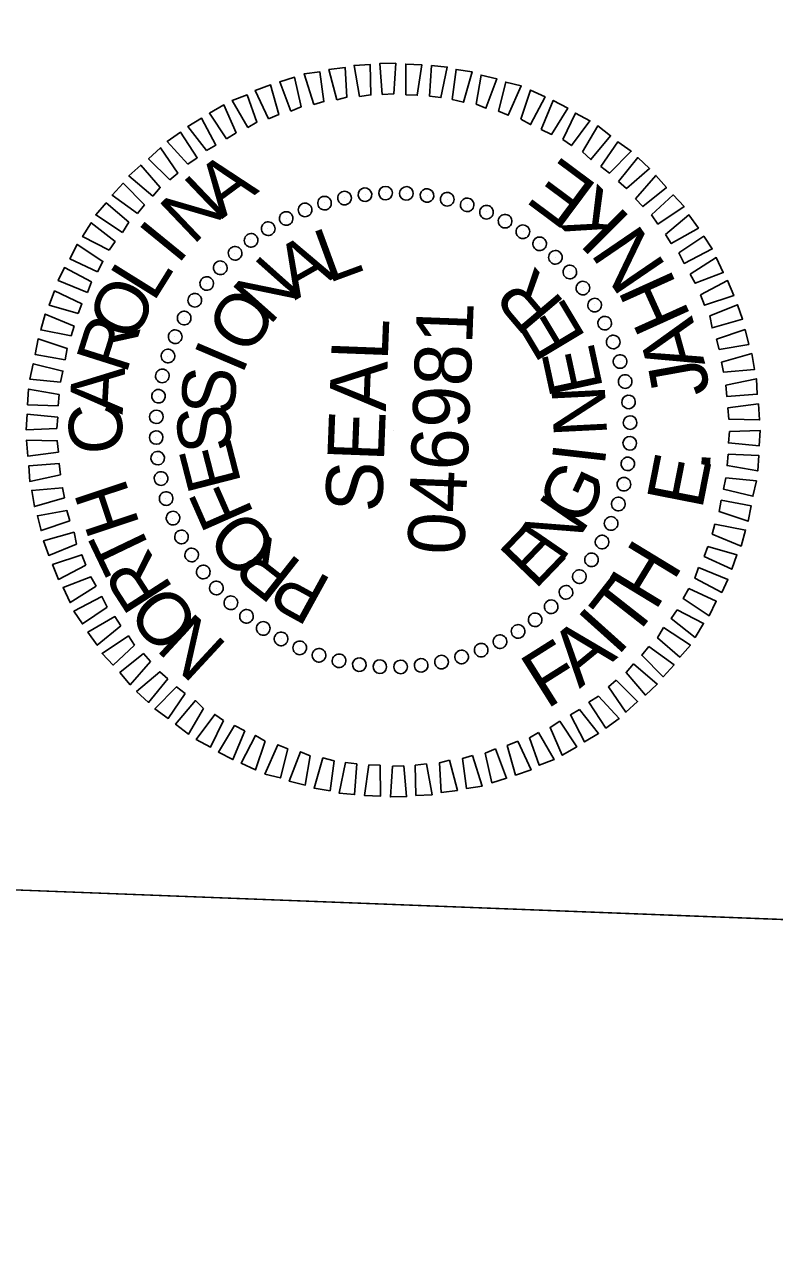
# Model space of a CAD drawing. Extents: x 2097096 to 2098260, y 686401 to 688363.
# Drawn here: x 2097223.6 to 2097303, y 687937.5 to 688066.3 of the extents above; entities that cross this region are included whole.
import ezdxf

# ---------------------------------------------------------------- set-up
doc = ezdxf.new("R2010")
doc.units = 0
for name, color, linetype in [('Sheet Layout Plan Border', 7, 'Continuous'), ('Sheet PE Seal Cell', 7, 'Continuous'), ('Sheet Profile CELL', 7, 'Continuous')]:
    doc.layers.add(name, color=color, linetype=linetype)

msp = doc.modelspace()

# ---------------------------------------------------------------- linework, layer by layer
at = {"layer": 'Sheet Layout Plan Border'}
msp.add_lwpolyline([(2098179.19, 686705.44), (2097129.59, 686735.95), (2097177.17, 687976.48), (2097364.33, 687969.3), (2097368.7, 688083.22), (2098230.76, 688050.16)], close=True, dxfattribs=at)
at = {"layer": 'Sheet PE Seal Cell'}
for p, q in [((2097259.66, 688048.29), (2097259.66, 688048.29)), ((2097261.82, 688048.51), (2097261.82, 688048.51)), ((2097264.02, 688048.47), (2097264.02, 688048.47)), ((2097255.33, 688047.46), (2097255.33, 688047.46)), ((2097257.45, 688047.98), (2097257.45, 688047.98)), ((2097266.22, 688048.24), (2097266.22, 688048.24)), ((2097268.35, 688047.81), (2097268.35, 688047.81)), ((2097270.43, 688047.28), (2097270.43, 688047.28)), ((2097251.31, 688045.81), (2097251.31, 688045.81)), ((2097253.3, 688046.73), (2097253.3, 688046.73)), ((2097272.51, 688046.5), (2097272.51, 688046.5)), ((2097249.37, 688044.73), (2097249.37, 688044.73)), ((2097274.47, 688045.52), (2097274.47, 688045.52)), ((2097276.38, 688044.45), (2097276.38, 688044.45)), ((2097247.57, 688043.55), (2097247.57, 688043.55)), ((2097278.13, 688043.13), (2097278.13, 688043.13)), ((2097245.87, 688042.12), (2097245.87, 688042.12)), ((2097244.31, 688040.62), (2097244.31, 688040.62)), ((2097279.83, 688041.71), (2097279.83, 688041.71)), ((2097281.32, 688040.16), (2097281.32, 688040.16)), ((2097242.89, 688038.93), (2097242.89, 688038.93)), ((2097282.75, 688038.45), (2097282.75, 688038.45)), ((2097241.58, 688037.18), (2097241.58, 688037.18)), ((2097283.94, 688036.65), (2097283.94, 688036.65)), ((2097240.5, 688035.27), (2097240.5, 688035.27)), ((2097285.01, 688034.71), (2097285.01, 688034.71)), ((2097239.53, 688033.3), (2097239.53, 688033.3)), ((2097285.94, 688032.72), (2097285.94, 688032.72)), ((2097238.75, 688031.23), (2097238.75, 688031.23)), ((2097286.66, 688030.69), (2097286.66, 688030.69)), ((2097238.22, 688029.15), (2097238.22, 688029.15)), ((2097287.18, 688028.57), (2097287.18, 688028.57)), ((2097237.78, 688027.01), (2097237.78, 688027.01)), ((2097287.49, 688026.36), (2097287.49, 688026.36)), ((2097237.55, 688024.82), (2097237.55, 688024.82)), ((2097287.71, 688024.2), (2097287.71, 688024.2)), ((2097237.51, 688022.62), (2097237.51, 688022.62)), ((2097262.61, 688023.41), (2097262.61, 688023.41)), ((2097287.68, 688022), (2097287.68, 688022)), ((2097237.73, 688020.46), (2097237.73, 688020.46)), ((2097287.44, 688019.81), (2097287.44, 688019.81)), ((2097238.05, 688018.25), (2097238.05, 688018.25)), ((2097287.01, 688017.67), (2097287.01, 688017.67)), ((2097238.57, 688016.13), (2097238.57, 688016.13)), ((2097286.48, 688015.59), (2097286.48, 688015.59)), ((2097239.29, 688014.1), (2097239.29, 688014.1)), ((2097285.7, 688013.52), (2097285.7, 688013.52)), ((2097240.21, 688012.11), (2097240.21, 688012.11)), ((2097284.73, 688011.55), (2097284.73, 688011.55)), ((2097241.29, 688010.17), (2097241.29, 688010.17)), ((2097283.65, 688009.64), (2097283.65, 688009.64)), ((2097242.47, 688008.37), (2097242.47, 688008.37)), ((2097282.33, 688007.89), (2097282.33, 688007.89)), ((2097243.91, 688006.66), (2097243.91, 688006.66)), ((2097280.92, 688006.2), (2097280.92, 688006.2)), ((2097245.4, 688005.11), (2097245.4, 688005.11)), ((2097279.36, 688004.7), (2097279.36, 688004.7)), ((2097247.1, 688003.69), (2097247.1, 688003.69)), ((2097277.65, 688003.27), (2097277.65, 688003.27)), ((2097248.85, 688002.37), (2097248.85, 688002.37)), ((2097275.86, 688002.09), (2097275.86, 688002.09)), ((2097250.76, 688001.3), (2097250.76, 688001.3)), ((2097273.91, 688001.01), (2097273.91, 688001.01)), ((2097252.72, 688000.32), (2097252.72, 688000.32)), ((2097254.79, 687999.54), (2097254.79, 687999.54)), ((2097269.9, 687999.36), (2097269.9, 687999.36)), ((2097271.93, 688000.09), (2097271.93, 688000.09)), ((2097256.87, 687999.01), (2097256.87, 687999.01)), ((2097259.01, 687998.58), (2097259.01, 687998.58)), ((2097261.2, 687998.35), (2097261.2, 687998.35)), ((2097263.4, 687998.31), (2097263.4, 687998.31)), ((2097265.56, 687998.53), (2097265.56, 687998.53)), ((2097267.78, 687998.84), (2097267.78, 687998.84))]:
    msp.add_line(p, q, dxfattribs=at)
for points in [[(2097254.23, 688057.86), (2097253.2, 688061.1), (2097254.86, 688061.33), (2097255.29, 688058.17)], [(2097256.65, 688058.36), (2097255.82, 688061.55), (2097257.53, 688061.78), (2097257.71, 688058.62)], [(2097259.06, 688058.72), (2097258.49, 688062), (2097260.19, 688062.08), (2097260.27, 688058.88)], [(2097261.47, 688058.93), (2097261.2, 688062.19), (2097262.9, 688062.23), (2097262.68, 688058.98)], [(2097263.97, 688058.88), (2097263.95, 688062.14), (2097265.65, 688062.07), (2097265.17, 688058.84)], [(2097266.47, 688058.74), (2097266.69, 688061.98), (2097268.34, 688061.82), (2097267.67, 688058.59)], [(2097268.86, 688058.4), (2097269.28, 688061.58), (2097270.97, 688061.32), (2097270.05, 688058.1)], [(2097249.42, 688056.34), (2097248.03, 688059.35), (2097249.65, 688059.93), (2097250.53, 688056.8)], [(2097251.8, 688057.15), (2097250.62, 688060.25), (2097252.19, 688060.74), (2097252.87, 688057.61)], [(2097271.39, 688057.9), (2097271.91, 688060.98), (2097273.6, 688060.57), (2097272.43, 688057.46)], [(2097273.76, 688057.16), (2097274.53, 688060.23), (2097276.17, 688059.82), (2097274.8, 688056.72)], [(2097247.23, 688055.42), (2097245.59, 688058.29), (2097247.16, 688058.88), (2097248.2, 688055.99)], [(2097276.13, 688056.32), (2097277.15, 688059.38), (2097278.68, 688058.67), (2097277.16, 688055.73)], [(2097244.98, 688054.21), (2097243.18, 688056.93), (2097244.72, 688057.82), (2097246.01, 688054.87)], [(2097278.29, 688055.23), (2097279.56, 688058.29), (2097281.08, 688057.48), (2097279.37, 688054.69)], [(2097242.88, 688052.99), (2097240.88, 688055.52), (2097242.36, 688056.41), (2097243.85, 688053.55)], [(2097280.55, 688054.15), (2097281.91, 688056.95), (2097283.43, 688056.14), (2097281.48, 688053.51)], [(2097240.88, 688051.56), (2097238.72, 688053.95), (2097240.11, 688054.95), (2097241.9, 688052.22)], [(2097282.66, 688052.86), (2097284.26, 688055.6), (2097285.62, 688054.55), (2097283.53, 688052.03)], [(2097284.6, 688051.29), (2097286.4, 688053.92), (2097287.81, 688052.92), (2097285.52, 688050.6)], [(2097239.01, 688049.88), (2097236.74, 688052.12), (2097237.99, 688053.28), (2097239.84, 688050.6)], [(2097286.44, 688049.72), (2097288.49, 688052.24), (2097289.74, 688051.09), (2097287.31, 688048.98)], [(2097237.19, 688048.15), (2097234.67, 688050.3), (2097235.92, 688051.45), (2097237.98, 688049.07)], [(2097288.27, 688047.89), (2097290.42, 688050.36), (2097291.52, 688049.07), (2097289.04, 688047.06)], [(2097235.57, 688046.31), (2097232.89, 688048.27), (2097234.04, 688049.52), (2097236.31, 688047.24)], [(2097289.96, 688046.18), (2097292.24, 688048.29), (2097293.39, 688047.05), (2097290.62, 688045.2)], [(2097233.99, 688044.32), (2097231.16, 688046.18), (2097232.26, 688047.44), (2097234.64, 688045.4)], [(2097291.43, 688044.12), (2097293.91, 688046.18), (2097294.91, 688044.79), (2097292.04, 688043.15)], [(2097232.57, 688042.43), (2097229.77, 688043.88), (2097230.68, 688045.35), (2097233.21, 688043.35)], [(2097292.85, 688042.16), (2097295.47, 688043.92), (2097296.37, 688042.58), (2097293.41, 688041.04)], [(2097231.33, 688040.17), (2097228.43, 688041.53), (2097229.19, 688043.06), (2097231.92, 688041.25)], [(2097230.3, 688037.96), (2097227.19, 688039.23), (2097227.85, 688040.61), (2097230.69, 688039.09)], [(2097294.02, 688039.92), (2097296.79, 688041.66), (2097297.53, 688040.08), (2097294.58, 688038.95)], [(2097229.31, 688035.75), (2097226.24, 688036.61), (2097226.8, 688038.14), (2097229.7, 688036.78)], [(2097295.14, 688037.72), (2097298, 688039.22), (2097298.64, 688037.64), (2097295.54, 688036.61)], [(2097296.1, 688035.49), (2097299.05, 688036.67), (2097299.59, 688035.15), (2097296.35, 688034.22)], [(2097228.57, 688033.37), (2097225.34, 688034), (2097225.81, 688035.68), (2097228.86, 688034.41)], [(2097227.92, 688030.84), (2097224.74, 688031.42), (2097225.06, 688033.06), (2097228.12, 688032.04)], [(2097296.81, 688033.01), (2097299.85, 688034.04), (2097300.24, 688032.47), (2097297.12, 688031.94)], [(2097297.36, 688030.58), (2097300.55, 688031.51), (2097300.84, 688029.8), (2097297.57, 688029.52)], [(2097227.43, 688028.46), (2097224.19, 688028.79), (2097224.55, 688030.42), (2097227.68, 688029.65)], [(2097227.19, 688025.97), (2097223.94, 688026.09), (2097224.05, 688027.74), (2097227.28, 688027.17)], [(2097297.82, 688028.16), (2097301.05, 688028.84), (2097301.14, 688027.19), (2097297.93, 688026.96)], [(2097227.04, 688023.57), (2097223.79, 688023.45), (2097223.9, 688025.09), (2097227.14, 688024.77)], [(2097298.03, 688025.75), (2097301.25, 688026.18), (2097301.38, 688024.48), (2097298.13, 688024.55)], [(2097298.18, 688023.25), (2097301.44, 688023.37), (2097301.33, 688021.73), (2097298.09, 688022.05)], [(2097227.2, 688021.07), (2097223.98, 688020.64), (2097223.84, 688022.34), (2097227.09, 688022.27)], [(2097298.04, 688020.85), (2097301.29, 688020.73), (2097301.18, 688019.08), (2097297.95, 688019.65)], [(2097227.41, 688018.66), (2097224.18, 688017.98), (2097224.09, 688019.63), (2097227.3, 688019.86)], [(2097297.8, 688018.36), (2097301.04, 688018.03), (2097300.67, 688016.4), (2097297.55, 688017.17)], [(2097227.86, 688016.24), (2097224.67, 688015.31), (2097224.39, 688017.02), (2097227.65, 688017.3)], [(2097228.42, 688013.81), (2097225.38, 688012.78), (2097224.99, 688014.35), (2097228.11, 688014.88)], [(2097297.3, 688015.98), (2097300.48, 688015.4), (2097300.17, 688013.76), (2097297.11, 688014.78)], [(2097229.13, 688011.33), (2097226.18, 688010.15), (2097225.64, 688011.67), (2097228.87, 688012.6)], [(2097296.66, 688013.45), (2097299.89, 688012.82), (2097299.42, 688011.14), (2097296.37, 688012.41)], [(2097295.92, 688011.07), (2097298.98, 688010.21), (2097298.43, 688008.68), (2097295.53, 688010.04)], [(2097230.09, 688009.1), (2097227.23, 688007.6), (2097226.59, 688009.18), (2097229.68, 688010.21)], [(2097294.93, 688008.86), (2097298.03, 688007.59), (2097297.38, 688006.22), (2097294.54, 688007.73)], [(2097231.21, 688006.9), (2097228.44, 688005.16), (2097227.7, 688006.74), (2097230.64, 688007.87)], [(2097232.37, 688004.66), (2097229.75, 688002.9), (2097228.85, 688004.24), (2097231.81, 688005.78)], [(2097293.89, 688006.65), (2097296.79, 688005.29), (2097296.04, 688003.76), (2097293.3, 688005.57)], [(2097233.8, 688002.7), (2097231.32, 688000.64), (2097230.32, 688002.03), (2097233.19, 688003.67)], [(2097292.66, 688004.39), (2097295.45, 688002.94), (2097294.55, 688001.47), (2097292.02, 688003.47)], [(2097291.23, 688002.5), (2097294.06, 688000.64), (2097292.96, 687999.38), (2097290.59, 688001.42)], [(2097235.27, 688000.64), (2097232.99, 687998.53), (2097231.83, 687999.77), (2097234.61, 688001.62)], [(2097236.96, 687998.93), (2097234.81, 687996.46), (2097233.71, 687997.75), (2097236.19, 687999.76)], [(2097289.66, 688000.51), (2097292.33, 687998.55), (2097291.18, 687997.3), (2097288.92, 687999.58)], [(2097288.03, 687998.67), (2097290.55, 687996.52), (2097289.31, 687995.37), (2097287.25, 687997.75)], [(2097238.79, 687997.1), (2097236.74, 687994.58), (2097235.48, 687995.73), (2097237.92, 687997.84)], [(2097286.22, 687996.94), (2097288.48, 687994.7), (2097287.24, 687993.54), (2097285.39, 687996.22)], [(2097240.63, 687995.53), (2097238.83, 687992.9), (2097237.41, 687993.9), (2097239.7, 687996.22)], [(2097242.57, 687993.96), (2097240.96, 687991.22), (2097239.6, 687992.27), (2097241.7, 687994.79)], [(2097284.35, 687995.26), (2097286.51, 687992.87), (2097285.12, 687991.87), (2097283.32, 687994.6)], [(2097244.67, 687992.67), (2097243.31, 687989.87), (2097241.79, 687990.68), (2097243.75, 687993.31)], [(2097282.34, 687993.83), (2097284.35, 687991.3), (2097282.86, 687990.41), (2097281.37, 687993.27)], [(2097246.93, 687991.59), (2097245.66, 687988.53), (2097244.14, 687989.34), (2097245.85, 687992.13)], [(2097280.25, 687992.61), (2097282.04, 687989.89), (2097280.51, 687989), (2097279.22, 687991.95)], [(2097249.09, 687990.5), (2097248.07, 687987.44), (2097246.55, 687988.15), (2097248.06, 687991.09)], [(2097275.81, 687990.48), (2097277.2, 687987.47), (2097275.57, 687986.89), (2097274.69, 687990.02)], [(2097278, 687991.4), (2097279.64, 687988.53), (2097278.07, 687987.94), (2097277.03, 687990.83)], [(2097251.46, 687989.66), (2097250.69, 687986.59), (2097249.06, 687987), (2097250.43, 687990.1)], [(2097253.84, 687988.92), (2097253.32, 687985.84), (2097251.63, 687986.25), (2097252.8, 687989.36)], [(2097273.43, 687989.67), (2097274.61, 687986.57), (2097273.04, 687986.08), (2097272.36, 687989.21)], [(2097256.37, 687988.42), (2097255.95, 687985.24), (2097254.25, 687985.5), (2097255.18, 687988.72)], [(2097258.76, 687988.08), (2097258.53, 687984.84), (2097256.89, 687985), (2097257.56, 687988.23)], [(2097261.25, 687987.94), (2097261.28, 687984.68), (2097259.58, 687984.75), (2097260.05, 687987.98)], [(2097263.75, 687987.89), (2097264.03, 687984.63), (2097262.33, 687984.59), (2097262.55, 687987.84)], [(2097266.16, 687988.1), (2097266.74, 687984.82), (2097265.03, 687984.74), (2097264.96, 687987.94)], [(2097268.58, 687988.46), (2097269.41, 687985.27), (2097267.7, 687985.04), (2097267.52, 687988.2)], [(2097271, 687988.96), (2097272.03, 687985.72), (2097270.37, 687985.49), (2097269.94, 687988.65)]]:
    msp.add_lwpolyline(points, close=True, dxfattribs=at)
for centre, major_axis in [((2097257.48, 688047.96), (-0.147, 0.705)), ((2097259.64, 688048.31), (-0.085, 0.715)), ((2097261.82, 688048.48), (-0.023, 0.72)), ((2097264.01, 688048.45), (0.04, 0.719)), ((2097266.19, 688048.23), (0.103, 0.713)), ((2097268.34, 688047.83), (0.164, 0.701)), ((2097253.3, 688046.7), (-0.267, 0.668)), ((2097255.36, 688047.42), (-0.208, 0.689)), ((2097270.45, 688047.24), (0.225, 0.684)), ((2097272.49, 688046.46), (0.284, 0.662)), ((2097251.3, 688045.8), (-0.325, 0.643)), ((2097274.46, 688045.51), (0.34, 0.635)), ((2097249.4, 688044.72), (-0.379, 0.612)), ((2097276.34, 688044.4), (0.394, 0.602)), ((2097247.59, 688043.49), (-0.431, 0.576)), ((2097278.12, 688043.12), (0.445, 0.566)), ((2097245.9, 688042.11), (-0.48, 0.537)), ((2097279.78, 688041.69), (0.493, 0.525)), ((2097244.33, 688040.58), (-0.525, 0.493)), ((2097281.31, 688040.13), (0.537, 0.48)), ((2097242.9, 688038.92), (-0.566, 0.445)), ((2097282.69, 688038.43), (0.576, 0.431)), ((2097241.63, 688037.14), (-0.602, 0.394)), ((2097283.93, 688036.63), (0.612, 0.379)), ((2097240.51, 688035.26), (-0.635, 0.34)), ((2097285, 688034.72), (0.643, 0.325)), ((2097239.56, 688033.29), (-0.662, 0.284)), ((2097285.9, 688032.73), (0.668, 0.267)), ((2097238.79, 688031.24), (-0.684, 0.225)), ((2097286.62, 688030.66), (0.689, 0.208)), ((2097238.2, 688029.14), (-0.701, 0.164)), ((2097287.16, 688028.54), (0.705, 0.147)), ((2097237.79, 688026.99), (-0.713, 0.103)), ((2097287.52, 688026.38), (0.715, 0.085)), ((2097237.57, 688024.81), (-0.719, 0.04)), ((2097287.68, 688024.2), (0.72, 0.023)), ((2097237.55, 688022.62), (-0.72, -0.023)), ((2097287.65, 688022.01), (0.719, -0.04)), ((2097237.71, 688020.44), (-0.715, -0.085)), ((2097287.44, 688019.83), (0.713, -0.103)), ((2097238.06, 688018.28), (-0.705, -0.147)), ((2097287.03, 688017.68), (0.701, -0.164)), ((2097238.6, 688016.16), (-0.689, -0.208)), ((2097286.44, 688015.58), (0.684, -0.225)), ((2097239.33, 688014.09), (-0.668, -0.267)), ((2097285.67, 688013.53), (0.662, -0.284)), ((2097240.23, 688012.1), (-0.643, -0.325)), ((2097284.72, 688011.56), (0.635, -0.34)), ((2097241.3, 688010.19), (-0.612, -0.379)), ((2097283.6, 688009.68), (0.602, -0.394)), ((2097242.53, 688008.39), (-0.576, -0.431)), ((2097282.32, 688007.9), (0.566, -0.445)), ((2097243.92, 688006.69), (-0.537, -0.48)), ((2097280.9, 688006.24), (0.525, -0.493)), ((2097245.45, 688005.13), (-0.493, -0.525)), ((2097247.1, 688003.7), (-0.445, -0.566)), ((2097279.33, 688004.71), (0.48, -0.537)), ((2097248.88, 688002.42), (-0.394, -0.602)), ((2097277.64, 688003.33), (0.431, -0.576)), ((2097250.76, 688001.31), (-0.34, -0.635)), ((2097275.83, 688002.1), (0.379, -0.612)), ((2097252.73, 688000.36), (-0.284, -0.662)), ((2097271.93, 688000.12), (0.267, -0.668)), ((2097273.92, 688001.02), (0.325, -0.643)), ((2097254.78, 687999.58), (-0.225, -0.684)), ((2097256.89, 687998.99), (-0.164, -0.701)), ((2097259.04, 687998.59), (-0.103, -0.713)), ((2097267.74, 687998.86), (0.147, -0.705)), ((2097269.86, 687999.4), (0.208, -0.689)), ((2097261.21, 687998.37), (-0.04, -0.719)), ((2097263.4, 687998.34), (0.023, -0.72)), ((2097265.58, 687998.51), (0.085, -0.715))]:
    msp.add_ellipse(centre, major_axis=major_axis, ratio=0.999708, dxfattribs=at)
at = {"layer": 'Sheet Profile CELL'}
msp.add_lwpolyline([(2097202.2, 687975.52), (2097206.03, 688075.5), (2097318.45, 688071.19), (2097314.61, 687971.21)], close=True, dxfattribs=at)

# ---------------------------------------------------------------- texts
at = {"layer": 'Sheet PE Seal Cell'}
for s, height, rotation, p in [('E', 6, 143.2967, (2097284.41, 688049.2)), ('A', 5.64, 36.4209, (2097244.51, 688045.72)), ('N', 5.64, 43.6226, (2097241.44, 688042.89)), ('K', 6, 135.0128, (2097287.9, 688045.79)), ('I', 5.64, 50.8238, (2097239.81, 688040.8)), ('L', 5.64, 20.2045, (2097255.75, 688038.93)), ('N', 6, 124.287, (2097291.62, 688040.69)), ('A', 5.64, 29.564, (2097252.23, 688037.12)), ('L', 5.64, 58.0246, (2097237.26, 688036.84)), ('N', 5.64, 48.2803, (2097249.52, 688034.37)), ('R', 5.64, 130.2851, (2097280.89, 688036.82)), ('H', 6, 114.303, (2097294.18, 688035.4)), ('O', 5.64, 65.2249, (2097235.24, 688032.52)), ('O', 5.64, 57.6372, (2097247.4, 688031.1)), ('E', 5.64, 120.9278, (2097283.1, 688033.18)), ('046981', 5.998, 87.8037, (2097270.12, 688010.14)), ('A', 6, 105.4627, (2097295.64, 688030.41)), ('R', 5.64, 72.4248, (2097234.36, 688029.2)), ('SEAL', 5.998, 87.8037, (2097261.43, 688014.65)), ('I', 5.64, 66.9933, (2097246.62, 688029.13)), ('E', 5.64, 102.2155, (2097284.85, 688027.81)), ('J', 6, 100.2049, (2097296.15, 688027.35)), ('A', 5.64, 86.824, (2097234, 688025.01)), ('S', 5.64, 85.7041, (2097245.76, 688024.86)), ('N', 5.64, 92.8601, (2097285.26, 688022.84)), ('C', 5.64, 94.0236, (2097234.15, 688021.05)), ('S', 5.64, 95.0593, (2097245.67, 688021.26)), ('E', 5.64, 104.4148, (2097246.59, 688017.77)), ('I', 5.64, 83.5049, (2097284.98, 688019.5)), ('E', 6, 78.8614, (2097295.28, 688014.87)), ('.', 6, 85.9707, (2097296.09, 688018.98)), ('G', 5.64, 64.7939, (2097282.83, 688013.03)), ('H', 5.64, 108.4232, (2097235.86, 688013.38)), ('F', 5.64, 113.7707, (2097247.96, 688014.51)), ('N', 5.64, 55.4377, (2097280.44, 688009.32)), ('O', 5.64, 132.4849, (2097250.78, 688011.1)), ('E', 5.64, 46.0806, (2097277.62, 688006.42)), ('T', 5.64, 115.6235, (2097237.38, 688010.07)), ('R', 5.64, 141.8433, (2097253.16, 688009.26)), ('H', 6, 58.677, (2097290.33, 688004.13)), ('R', 5.64, 122.8242, (2097239.45, 688006.59)), ('T', 6, 51.8768, (2097287.85, 688000.98)), ('P', 5.64, 151.2026, (2097256.3, 688007.54)), ('O', 5.64, 130.0254, (2097242.42, 688003.02)), ('I', 6, 48.0749, (2097286.31, 687999.36)), ('N', 5.64, 137.2272, (2097245.23, 688000.61)), ('A', 6, 39.2346, (2097282.33, 687996)), ('F', 6, 32.2179, (2097278.83, 687993.8))]:
    msp.add_text(s, height=height, rotation=rotation, dxfattribs=at).set_placement(p)

doc.saveas('drawing.dxf')
